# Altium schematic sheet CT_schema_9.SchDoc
size 402 x 245 mm
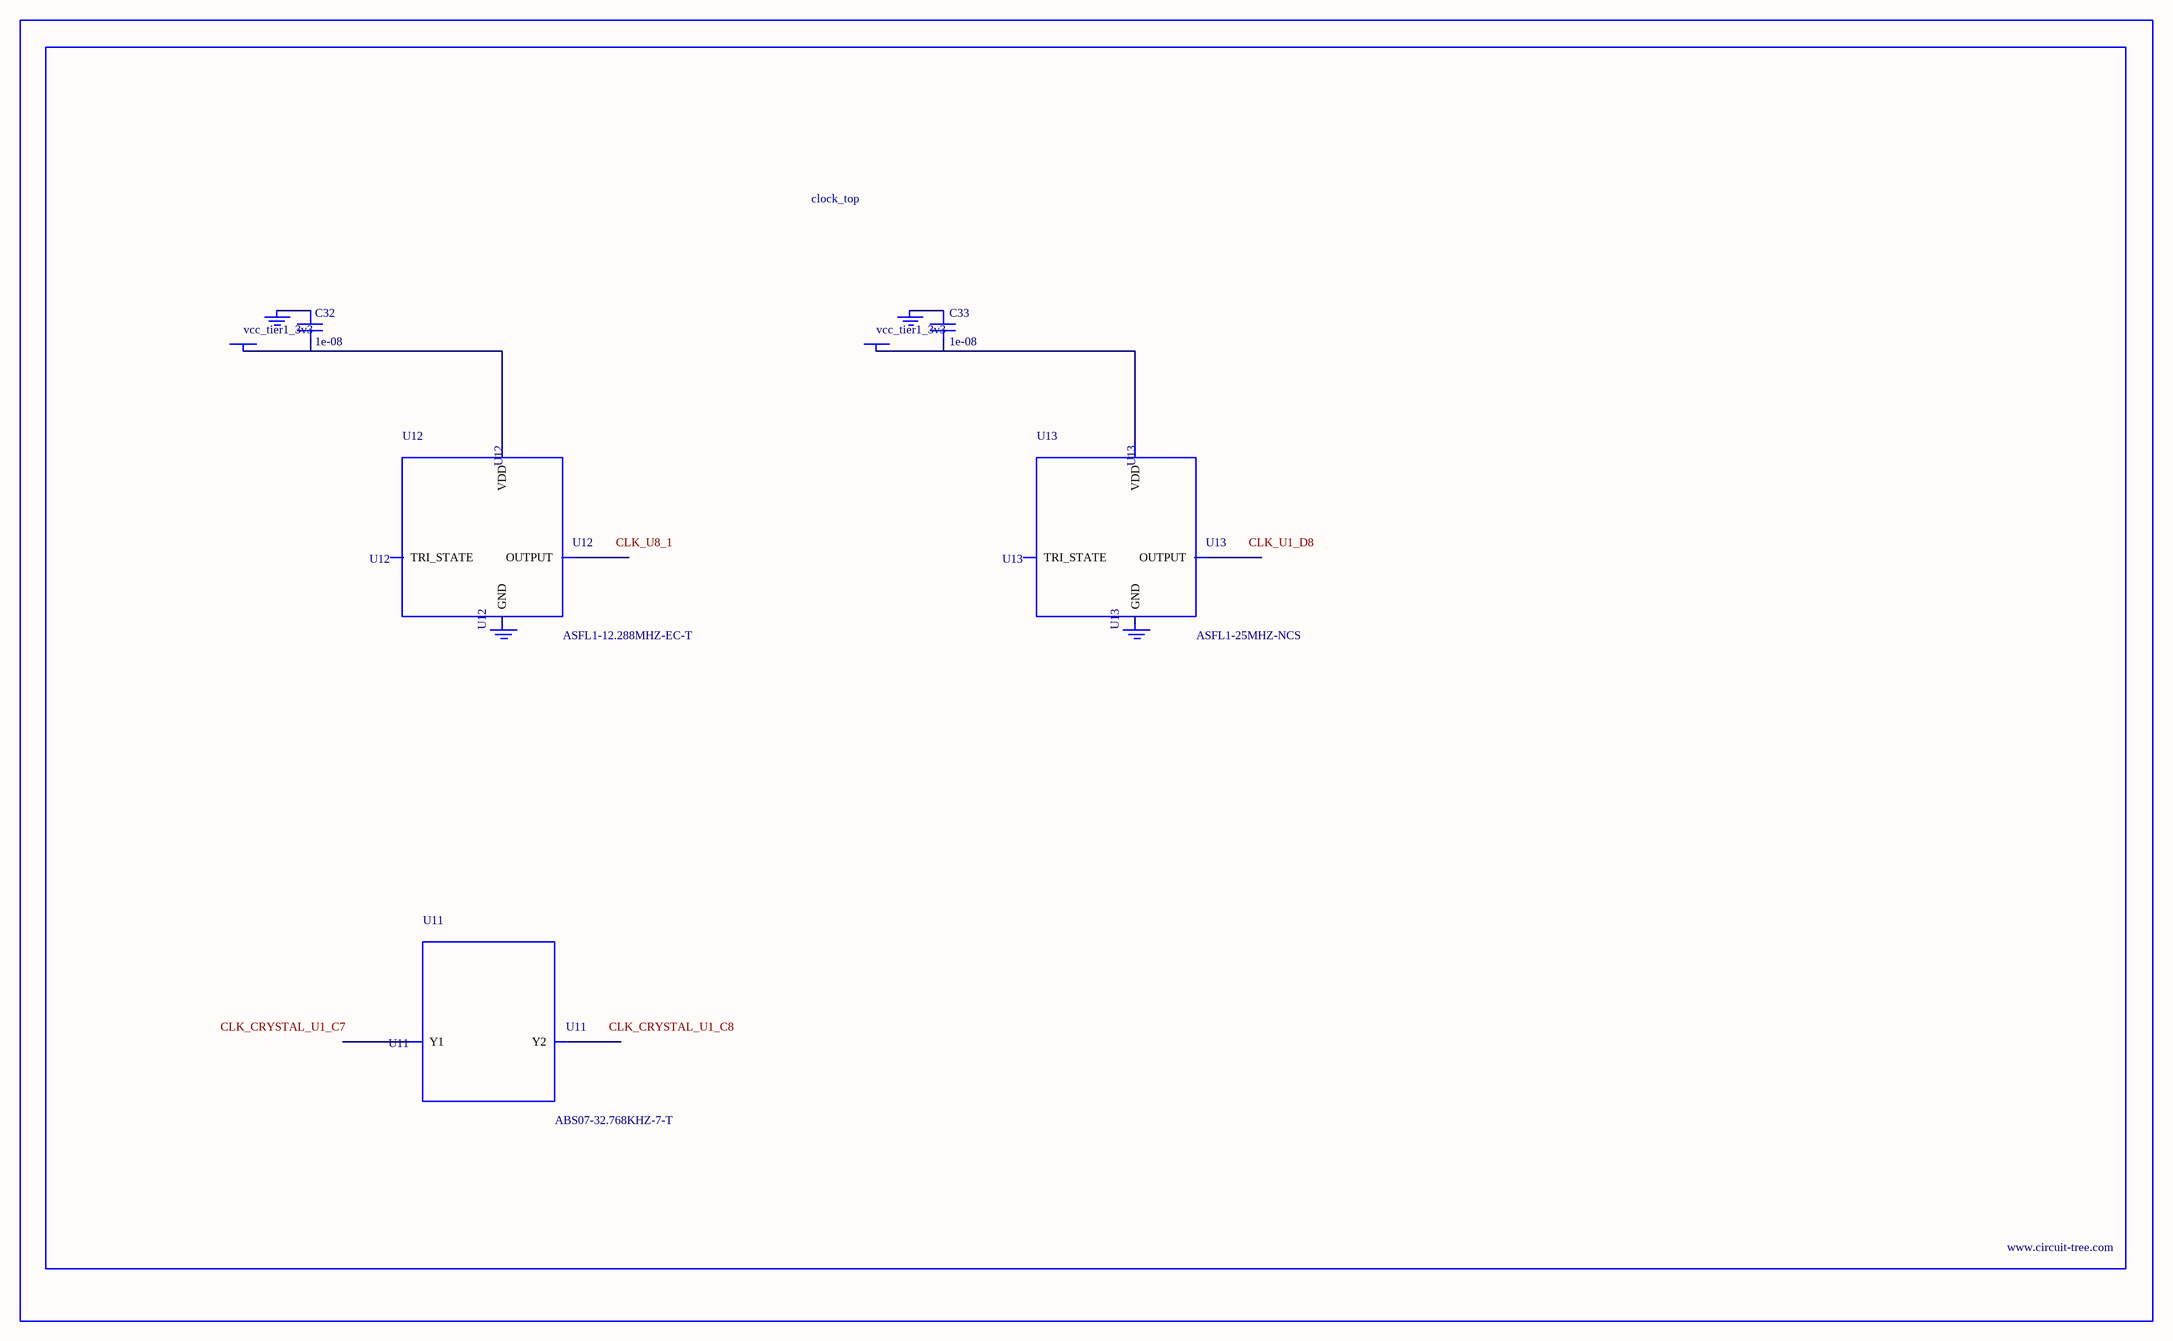
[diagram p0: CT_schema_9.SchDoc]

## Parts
BORDER8  (no value)
C32  1e-08  [C0402]
C33  1e-08  [C0402]
GND_INSTANCE_8_0  (no value)
GND_INSTANCE_8_1  (no value)
GND_INSTANCE_8_2  (no value)
GND_INSTANCE_8_3  (no value)
POWER_INSTANCE_8_0  vcc_tier1_3v3
POWER_INSTANCE_8_1  vcc_tier1_3v3
U11  ABS07-32.768KHZ-7-T  [ABS07-32.768KHZ-7-T]
U12  ASFL1-12.288MHZ-EC-T  [ASFL1]
U13  ASFL1-25MHZ-NCS  [ASFL1]

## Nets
NetC32_1: C32.1 GND_INSTANCE_8_0.0(GND)
NetC32_2: C32.2 POWER_INSTANCE_8_0.0(PWR) U12.4(VDD)
NetC33_1: C33.1 GND_INSTANCE_8_2.0(GND)
NetC33_2: C33.2 POWER_INSTANCE_8_1.0(PWR) U13.4(VDD)

Not connected (* = marked no-connect by the designer): GND_INSTANCE_8_1 0(GND); GND_INSTANCE_8_3 0(GND); U11 1(Y1) 2(Y2); U12 1(TRI_STATE) 2(GND) 3(OUTPUT); U13 1(TRI_STATE) 2(GND) 3(OUTPUT)

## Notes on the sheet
- Labels drawn without touching a wire or pin: CLK_CRYSTAL_U1_C7, CLK_CRYSTAL_U1_C8, CLK_U1_D8, CLK_U8_1

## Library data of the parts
BORDER8 = BORDER_PAGE8
C32 C33 = C0402C103K3RAC
GND_INSTANCE_8_0-GND_INSTANCE_8_3 = GND
POWER_INSTANCE_8_0 POWER_INSTANCE_8_1 = PWR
